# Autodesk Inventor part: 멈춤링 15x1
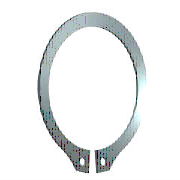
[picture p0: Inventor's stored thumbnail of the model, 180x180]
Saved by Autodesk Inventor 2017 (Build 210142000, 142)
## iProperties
Created: 2015-09
Part Number: 멈춤링 15x1
Material: 강, 연강
Description: 리테이닝 링(C형)
Document SubType Name: Modeling
Standard: KS B 1336
Designer: mm
Standards Organization: KS
Language: ko-KR
Size Designation: 15 x 1
Categories: <MemberInstance><Categories><Category DisplayName="샤프트 부품" InternalName="7f7aeb1f-a693-4053-b835-cee3144e0d98" Mnemonic="SHFT"><Category DisplayName="써클립" Inter
Density: 1 g/cm^3
Appearance: 파란색 - 벽 페인트 - 광택
IsCustomPart: 1
Author: mduedu
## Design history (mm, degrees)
sketch "스케치1"
  geometry: L1 (-6, 0)-(6, 0) reference; L2 (0, 20.189)-(0, -80.536) reference; L3 (-48.09, 0)-(48.09, 0) reference; L4 (-0.425, -14.637)-(-0.425, -18.137); L5 (-0.425, -6.54)-(-0.425, -13.29); L6 (-2.795, 2.1)-(3.672, 2.1); L7 (0.425, -6.54)-(0.425, -13.29); L8 (0.425, -14.637)-(0.425, -18.137); C1 r 0.85 at (-1.7, -16.283); C2 r 0.85 at (1.7, -16.283); A1 r 7.15 centre (0, -7.5) between (0.425, -14.637) and (-0.425, -14.637); A2 r 9.075 centre (0, -6.975) between (4.291, -14.971) and (-4.291, -14.971); A3 r 10.646 centre (0, -7.5) between (-2.023, -17.952) and (-0.425, -18.137); A4 r 1.7 centre (-1.7, -16.283) between (-3.397, -16.376) and (-2.023, -17.952); A5 r 1.7 centre (-5.095, -16.469) between (-3.397, -16.376) and (-4.291, -14.971); A6 r 1.7 centre (5.095, -16.469) between (4.291, -14.971) and (3.397, -16.376); A7 r 1.7 centre (1.7, -16.283) between (2.023, -17.952) and (3.397, -16.376); A8 r 10.646 centre (0, -7.5) between (0.425, -18.137) and (2.023, -17.952)
  constraints: 16 point on circle, 12 end point, 10 centre point, 9 symmetric about line, 5 point on line, 4 tangent, 3 coincident, 2 horizontal, 1 perpendicular, 1 vertical, 5 other
  dimensions: "d0" = 14.3 diameter of A1 (= ND); "d1" = 3.5 distance of L4.end L4.start (= SRB2); "d6" = 0.425 distance between parallel lines of L2 L5 (= 0.25 x SD5); "d7" = 2.1 distance between parallel lines of L6 L3 (= SRB1); "d8" = 0.525 distance of A1.centre A2.centre (= 0.25 x SRB1); "d9" = 1.7 radius of A4 (= SD5); "d10" = 1.7 radius of A5 (= SD5); "d11" = 1.275 distance from line of L4 A4.centre (= 0.75 x SD5); "d12" = 1.7 diameter of C1 (= SD5); "d13" = 1.7 diameter of C2 (= SD5); "d14" = 7.5 distance from line of A1.centre L1 (= 0.5 x WD)
extrude "본체" new body sketch "스케치1" distance "d2" = 1 (= SD); taper "d3" = 0 deg
workaxis "Work Axis1"
workplane "Work Plane1"
body "Solid1"
other parameters: "WD" = 15 (= WDMIN) [user parameter; used in 1 equation term], "SD" = 1 [user parameter; used in 1 equation term], "SRB1" = 2.1 [user parameter; used in 2 equation terms], "ND" = 14.3 [user parameter; used in 1 equation term], "SRB2" = 3.5 [user parameter; used in 1 equation term], "SD5" = 1.7 [user parameter; used in 6 equation terms], "d15" = 0, "d16" = 0, "d17" = 0, "d41" = 0, "d42" = 0, "WDMIN" = 15 [user parameter; used in 1 equation term], "SD3" = 13.8 [user parameter], "WDMAX" = 16 [user parameter]
